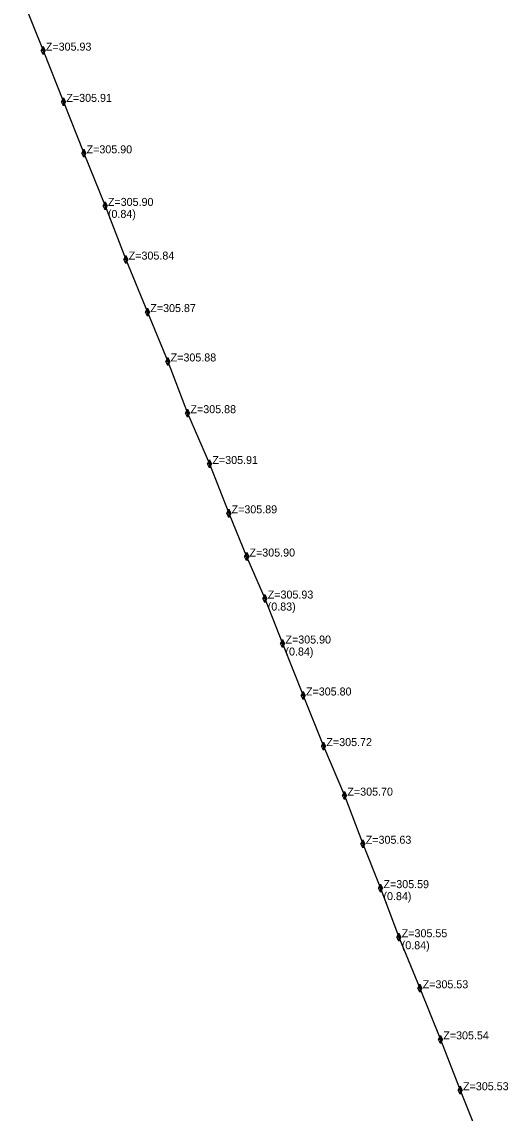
# Model space of a CAD drawing. Extents: x 799271 to 799523, y 67737 to 68184.
# Drawn here: x 799408.2 to 799432.5, y 67849.8 to 67904.3 of the extents above; entities that cross this region are included whole.
import ezdxf

# ---------------------------------------------------------------- set-up
doc = ezdxf.new("R2010")
doc.units = 0
doc.layers.add('PGOC_HTA_CONSTRUIT', color=7, linetype='Continuous')
doc.layers.add('PGOC_PTRL', color=7, linetype='Continuous')

msp = doc.modelspace()

# ---------------------------------------------------------------- linework, layer by layer
at = {"layer": 'PGOC_HTA_CONSTRUIT'}
msp.add_lwpolyline([(799408.246, 67905.536), (799409.304, 67902.864), (799410.328, 67900.303), (799411.338, 67897.732), (799412.402, 67895.104), (799413.441, 67892.422), (799414.519, 67889.799), (799415.535, 67887.331), (799416.525, 67884.747), (799417.62, 67882.208), (799418.577, 67879.742), (799419.471, 67877.583), (799420.382, 67875.483), (799421.267, 67873.236), (799422.291, 67870.639), (799423.312, 67868.11), (799424.359, 67865.634), (799425.277, 67863.23), (799426.161, 67861.012), (799427.073, 67858.559), (799428.119, 67856.008), (799429.147, 67853.455), (799430.135, 67850.913), (799431.122, 67848.416)], dxfattribs=at)
at = {"layer": 'PGOC_PTRL'}
for points in [[(799409.204, 67902.864), (799409.304, 67903.064), (799409.404, 67902.864), (799409.304, 67902.664), (799409.204, 67902.864)], [(799409.404, 67902.864), (799409.304, 67902.864), (799409.204, 67902.864)], [(799409.304, 67903.064), (799409.304, 67902.664)], [(799410.228, 67900.303), (799410.328, 67900.503), (799410.428, 67900.303), (799410.328, 67900.103), (799410.228, 67900.303)], [(799410.328, 67900.503), (799410.328, 67900.103)], [(799410.428, 67900.303), (799410.328, 67900.303), (799410.228, 67900.303)], [(799411.238, 67897.732), (799411.338, 67897.932), (799411.438, 67897.732), (799411.338, 67897.532), (799411.238, 67897.732)], [(799411.438, 67897.732), (799411.338, 67897.732), (799411.238, 67897.732)], [(799411.338, 67897.932), (799411.338, 67897.532)], [(799412.302, 67895.104), (799412.402, 67895.304), (799412.502, 67895.104), (799412.402, 67894.904), (799412.302, 67895.104)], [(799412.502, 67895.104), (799412.402, 67895.104), (799412.302, 67895.104)], [(799412.402, 67895.304), (799412.402, 67894.904)], [(799413.341, 67892.422), (799413.441, 67892.622), (799413.541, 67892.422), (799413.441, 67892.222), (799413.341, 67892.422)], [(799413.541, 67892.422), (799413.441, 67892.422), (799413.341, 67892.422)], [(799413.441, 67892.622), (799413.441, 67892.222)], [(799414.419, 67889.799), (799414.519, 67889.999), (799414.619, 67889.799), (799414.519, 67889.599), (799414.419, 67889.799)], [(799414.519, 67889.999), (799414.519, 67889.599)], [(799414.619, 67889.799), (799414.519, 67889.799), (799414.419, 67889.799)], [(799415.435, 67887.331), (799415.535, 67887.531), (799415.635, 67887.331), (799415.535, 67887.131), (799415.435, 67887.331)], [(799415.635, 67887.331), (799415.535, 67887.331), (799415.435, 67887.331)], [(799415.535, 67887.531), (799415.535, 67887.131)], [(799416.425, 67884.747), (799416.525, 67884.947), (799416.625, 67884.747), (799416.525, 67884.547), (799416.425, 67884.747)], [(799416.625, 67884.747), (799416.525, 67884.747), (799416.425, 67884.747)], [(799416.525, 67884.947), (799416.525, 67884.547)], [(799417.52, 67882.208), (799417.62, 67882.408), (799417.72, 67882.208), (799417.62, 67882.008), (799417.52, 67882.208)], [(799417.62, 67882.408), (799417.62, 67882.008)], [(799417.72, 67882.208), (799417.62, 67882.208), (799417.52, 67882.208)], [(799418.477, 67879.742), (799418.577, 67879.942), (799418.677, 67879.742), (799418.577, 67879.542), (799418.477, 67879.742)], [(799418.677, 67879.742), (799418.577, 67879.742), (799418.477, 67879.742)], [(799418.577, 67879.942), (799418.577, 67879.542)], [(799419.371, 67877.583), (799419.471, 67877.783), (799419.571, 67877.583), (799419.471, 67877.383), (799419.371, 67877.583)], [(799419.571, 67877.583), (799419.471, 67877.583), (799419.371, 67877.583)], [(799419.471, 67877.783), (799419.471, 67877.383)], [(799420.282, 67875.483), (799420.382, 67875.683), (799420.482, 67875.483), (799420.382, 67875.283), (799420.282, 67875.483)], [(799420.482, 67875.483), (799420.382, 67875.483), (799420.282, 67875.483)], [(799420.382, 67875.683), (799420.382, 67875.283)], [(799421.167, 67873.236), (799421.267, 67873.436), (799421.367, 67873.236), (799421.267, 67873.036), (799421.167, 67873.236)], [(799421.367, 67873.236), (799421.267, 67873.236), (799421.167, 67873.236)], [(799421.267, 67873.436), (799421.267, 67873.036)], [(799422.191, 67870.639), (799422.291, 67870.839), (799422.391, 67870.639), (799422.291, 67870.439), (799422.191, 67870.639)], [(799422.391, 67870.639), (799422.291, 67870.639), (799422.191, 67870.639)], [(799422.291, 67870.839), (799422.291, 67870.439)], [(799423.212, 67868.11), (799423.312, 67868.31), (799423.412, 67868.11), (799423.312, 67867.91), (799423.212, 67868.11)], [(799423.312, 67868.31), (799423.312, 67867.91)], [(799423.412, 67868.11), (799423.312, 67868.11), (799423.212, 67868.11)], [(799424.259, 67865.634), (799424.359, 67865.834), (799424.459, 67865.634), (799424.359, 67865.434), (799424.259, 67865.634)], [(799424.459, 67865.634), (799424.359, 67865.634), (799424.259, 67865.634)], [(799424.359, 67865.834), (799424.359, 67865.434)], [(799425.177, 67863.23), (799425.277, 67863.43), (799425.377, 67863.23), (799425.277, 67863.03), (799425.177, 67863.23)], [(799425.277, 67863.43), (799425.277, 67863.03)], [(799425.377, 67863.23), (799425.277, 67863.23), (799425.177, 67863.23)], [(799426.061, 67861.012), (799426.161, 67861.212), (799426.261, 67861.012), (799426.161, 67860.812), (799426.061, 67861.012)], [(799426.161, 67861.212), (799426.161, 67860.812)], [(799426.261, 67861.012), (799426.161, 67861.012), (799426.061, 67861.012)], [(799426.973, 67858.559), (799427.073, 67858.759), (799427.173, 67858.559), (799427.073, 67858.359), (799426.973, 67858.559)], [(799427.173, 67858.559), (799427.073, 67858.559), (799426.973, 67858.559)], [(799427.073, 67858.759), (799427.073, 67858.359)], [(799428.019, 67856.008), (799428.119, 67856.208), (799428.219, 67856.008), (799428.119, 67855.808), (799428.019, 67856.008)], [(799428.119, 67856.208), (799428.119, 67855.808)], [(799428.219, 67856.008), (799428.119, 67856.008), (799428.019, 67856.008)], [(799429.047, 67853.455), (799429.147, 67853.655), (799429.247, 67853.455), (799429.147, 67853.255), (799429.047, 67853.455)], [(799429.247, 67853.455), (799429.147, 67853.455), (799429.047, 67853.455)], [(799429.147, 67853.655), (799429.147, 67853.255)], [(799430.035, 67850.913), (799430.135, 67851.113), (799430.235, 67850.913), (799430.135, 67850.713), (799430.035, 67850.913)], [(799430.235, 67850.913), (799430.135, 67850.913), (799430.035, 67850.913)], [(799430.135, 67851.113), (799430.135, 67850.713)]]:
    msp.add_lwpolyline(points, dxfattribs=at)

# ---------------------------------------------------------------- texts
for s, p in [('Z=305.93', (799409.444, 67902.864)), ('Z=305.91', (799410.468, 67900.303)), ('Z=305.90', (799411.478, 67897.732)), ('Z=305.90', (799412.542, 67895.104)), ('(0.84)', (799412.542, 67894.504)), ('Z=305.84', (799413.581, 67892.422)), ('Z=305.87', (799414.659, 67889.799)), ('Z=305.88', (799415.675, 67887.331)), ('Z=305.88', (799416.665, 67884.747)), ('Z=305.91', (799417.76, 67882.208)), ('Z=305.89', (799418.717, 67879.742)), ('Z=305.90', (799419.611, 67877.583)), ('Z=305.93', (799420.522, 67875.483)), ('(0.83)', (799420.522, 67874.883)), ('Z=305.90', (799421.407, 67873.236)), ('(0.84)', (799421.407, 67872.636)), ('Z=305.80', (799422.431, 67870.639)), ('Z=305.72', (799423.452, 67868.11)), ('Z=305.70', (799424.499, 67865.634)), ('Z=305.63', (799425.417, 67863.23)), ('Z=305.59', (799426.301, 67861.012)), ('(0.84)', (799426.301, 67860.412)), ('Z=305.55', (799427.213, 67858.559)), ('(0.84)', (799427.213, 67857.959)), ('Z=305.53', (799428.259, 67856.008)), ('Z=305.54', (799429.287, 67853.455)), ('Z=305.53', (799430.275, 67850.913))]:
    msp.add_text(s, height=0.4, dxfattribs=at).set_placement(p)

doc.saveas('drawing.dxf')
